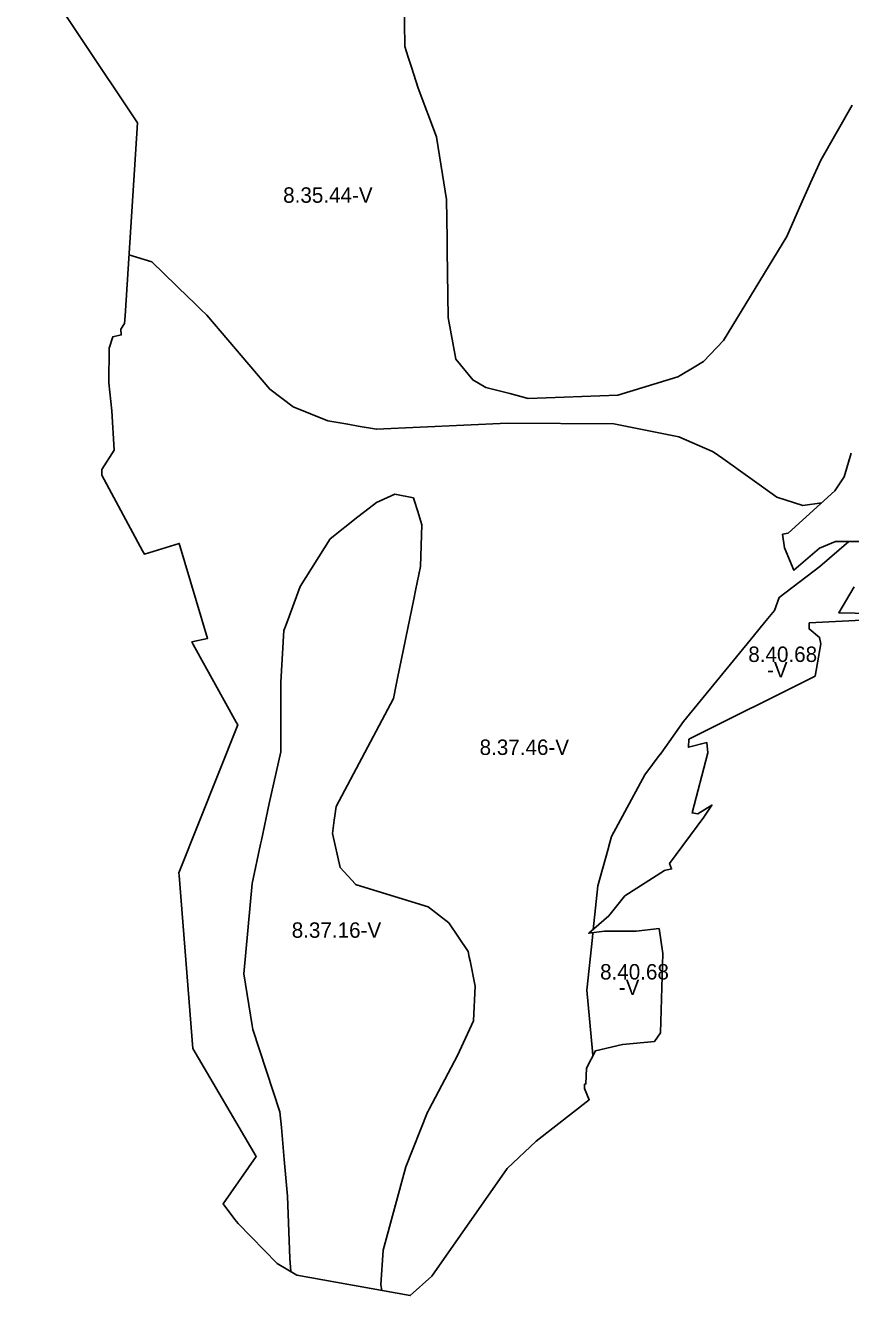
# Model space of a CAD drawing. Extents: x -547623 to -533936, y -1096714 to -1086523.
# Drawn here: x -545672 to -545138, y -1093937 to -1093114 of the extents above; entities that cross this region are included whole.
import ezdxf

# ---------------------------------------------------------------- set-up
doc = ezdxf.new("R2010")
doc.units = 0
doc.layers.add('Vrstva 27', color=7, linetype='Continuous')
doc.layers.add('Vrstva 28', color=7, linetype='Continuous')

msp = doc.modelspace()

# ---------------------------------------------------------------- linework, layer by layer
at = {"layer": 'Vrstva 28'}
for p, q in [((-545426.5, -1093127.5), (-545427, -1093096)), ((-545427, -1093096), (-545426.5, -1093127.5)), ((-545424.37, -1093134.25), (-545426.5, -1093127.5)), ((-545426.5, -1093127.5), (-545424.37, -1093134.25)), ((-545422.33, -1093140.76), (-545424.37, -1093134.25)), ((-545424.37, -1093134.25), (-545422.33, -1093140.76)), ((-545418, -1093154.5), (-545422.33, -1093140.76)), ((-545422.33, -1093140.76), (-545418, -1093154.5)), ((-545406, -1093186), (-545418, -1093154.5)), ((-545418, -1093154.5), (-545406, -1093186)), ((-545136.5, -1093165.5), (-545157, -1093201)), ((-545157, -1093201), (-545136.5, -1093165.5)), ((-545405.76, -1093187.52), (-545406, -1093186)), ((-545406, -1093186), (-545405.76, -1093187.52)), ((-545399.5, -1093226.5), (-545405.76, -1093187.52)), ((-545405.76, -1093187.52), (-545399.5, -1093226.5)), ((-545157, -1093201), (-545163.53, -1093215.69)), ((-545163.53, -1093215.69), (-545157, -1093201)), ((-545163.53, -1093215.69), (-545170.69, -1093231.81)), ((-545170.69, -1093231.81), (-545163.53, -1093215.69)), ((-545399.16, -1093252.14), (-545399.5, -1093226.5)), ((-545399.5, -1093226.5), (-545399.16, -1093252.14)), ((-545170.69, -1093231.81), (-545179, -1093250.5)), ((-545179, -1093250.5), (-545170.69, -1093231.81)), ((-545399.11, -1093256.04), (-545399.16, -1093252.14)), ((-545399.16, -1093252.14), (-545399.11, -1093256.04)), ((-545399.07, -1093259.54), (-545399.11, -1093256.04)), ((-545399.11, -1093256.04), (-545399.07, -1093259.54)), ((-545179, -1093250.5), (-545220, -1093318)), ((-545220, -1093318), (-545179, -1093250.5)), ((-545590.5, -1093267), (-545605.36, -1093262.54)), ((-545605.36, -1093262.54), (-545590.5, -1093267)), ((-545605.36, -1093262.54), (-545605.36, -1093262.54)), ((-545605.36, -1093262.54), (-545605.36, -1093262.54)), ((-545398.5, -1093303), (-545399.07, -1093259.54)), ((-545399.07, -1093259.54), (-545398.5, -1093303)), ((-545566.68, -1093290.14), (-545590.5, -1093267)), ((-545590.5, -1093267), (-545566.68, -1093290.14)), ((-545563.28, -1093293.45), (-545566.68, -1093290.14)), ((-545566.68, -1093290.14), (-545563.28, -1093293.45)), ((-545559.04, -1093297.57), (-545563.28, -1093293.45)), ((-545563.28, -1093293.45), (-545559.04, -1093297.57)), ((-545555, -1093301.5), (-545559.04, -1093297.57)), ((-545559.04, -1093297.57), (-545555, -1093301.5)), ((-545514, -1093349.5), (-545555, -1093301.5)), ((-545555, -1093301.5), (-545514, -1093349.5)), ((-545393.5, -1093330), (-545398.5, -1093303)), ((-545398.5, -1093303), (-545393.5, -1093330)), ((-545220, -1093318), (-545233, -1093331.5)), ((-545233, -1093331.5), (-545220, -1093318)), ((-545382.5, -1093343.5), (-545393.5, -1093330)), ((-545393.5, -1093330), (-545382.5, -1093343.5)), ((-545239.09, -1093335.19), (-545248.07, -1093340.63)), ((-545248.07, -1093340.63), (-545239.09, -1093335.19)), ((-545233, -1093331.5), (-545239.09, -1093335.19)), ((-545239.09, -1093335.19), (-545233, -1093331.5)), ((-545374, -1093348.5), (-545382.5, -1093343.5)), ((-545382.5, -1093343.5), (-545374, -1093348.5)), ((-545249.5, -1093341.5), (-545288.5, -1093353.5)), ((-545288.5, -1093353.5), (-545249.5, -1093341.5)), ((-545248.07, -1093340.63), (-545249.5, -1093341.5)), ((-545249.5, -1093341.5), (-545248.07, -1093340.63)), ((-545499, -1093361), (-545514, -1093349.5)), ((-545514, -1093349.5), (-545499, -1093361)), ((-545358.57, -1093352.43), (-545374, -1093348.5)), ((-545374, -1093348.5), (-545358.57, -1093352.43)), ((-545348.97, -1093354.87), (-545358.57, -1093352.43)), ((-545358.57, -1093352.43), (-545348.97, -1093354.87)), ((-545346.5, -1093355.5), (-545348.97, -1093354.87)), ((-545348.97, -1093354.87), (-545346.5, -1093355.5)), ((-545288.5, -1093353.5), (-545346.5, -1093355.5)), ((-545346.5, -1093355.5), (-545288.5, -1093353.5)), ((-545476.5, -1093370), (-545499, -1093361)), ((-545499, -1093361), (-545476.5, -1093370)), ((-545463.57, -1093372.26), (-545476.5, -1093370)), ((-545476.5, -1093370), (-545463.57, -1093372.26)), ((-545360, -1093371.5), (-545445, -1093375.5)), ((-545445, -1093375.5), (-545360, -1093371.5)), ((-545291, -1093372), (-545360, -1093371.5)), ((-545360, -1093371.5), (-545291, -1093372)), ((-545456.9, -1093373.42), (-545463.57, -1093372.26)), ((-545463.57, -1093372.26), (-545456.9, -1093373.42)), ((-545445, -1093375.5), (-545456.9, -1093373.42)), ((-545456.9, -1093373.42), (-545445, -1093375.5)), ((-545249, -1093380.5), (-545291, -1093372)), ((-545291, -1093372), (-545249, -1093380.5)), ((-545227.2, -1093389.98), (-545249, -1093380.5)), ((-545249, -1093380.5), (-545227.2, -1093389.98)), ((-545226, -1093390.5), (-545227.2, -1093389.98)), ((-545227.2, -1093389.98), (-545226, -1093390.5)), ((-545220.43, -1093394.49), (-545226, -1093390.5)), ((-545226, -1093390.5), (-545220.43, -1093394.49)), ((-545185.5, -1093419.5), (-545220.43, -1093394.49)), ((-545220.43, -1093394.49), (-545185.5, -1093419.5)), ((-545445, -1093423), (-545433, -1093417.5)), ((-545433, -1093417.5), (-545445, -1093423)), ((-545433, -1093417.5), (-545421, -1093420)), ((-545421, -1093420), (-545433, -1093417.5)), ((-545421, -1093420), (-545420.54, -1093421.46)), ((-545420.54, -1093421.46), (-545421, -1093420)), ((-545168.5, -1093425), (-545185.5, -1093419.5)), ((-545185.5, -1093419.5), (-545168.5, -1093425)), ((-545456.95, -1093432.36), (-545449.58, -1093426.59)), ((-545449.58, -1093426.59), (-545456.95, -1093432.36)), ((-545449.58, -1093426.59), (-545445, -1093423)), ((-545445, -1093423), (-545449.58, -1093426.59)), ((-545420.54, -1093421.46), (-545418.2, -1093428.91)), ((-545418.2, -1093428.91), (-545420.54, -1093421.46)), ((-545418.2, -1093428.91), (-545415.5, -1093437.5)), ((-545415.5, -1093437.5), (-545418.2, -1093428.91)), ((-545156.28, -1093423.14), (-545168.5, -1093425)), ((-545168.5, -1093425), (-545156.28, -1093423.14)), ((-545156.28, -1093423.14), (-545156.28, -1093423.14)), ((-545156.28, -1093423.14), (-545156.28, -1093423.14)), ((-545475, -1093446.5), (-545456.95, -1093432.36)), ((-545456.95, -1093432.36), (-545475, -1093446.5)), ((-545415.5, -1093437.5), (-545416.5, -1093464.5)), ((-545416.5, -1093464.5), (-545415.5, -1093437.5)), ((-545494.5, -1093477.5), (-545475, -1093446.5)), ((-545475, -1093446.5), (-545494.5, -1093477.5)), ((-545138.7, -1093448.27), (-545157.5, -1093464.5)), ((-545157.5, -1093464.5), (-545138.7, -1093448.27)), ((-545416.5, -1093464.5), (-545419.69, -1093480.07)), ((-545419.69, -1093480.07), (-545416.5, -1093464.5)), ((-545157.5, -1093464.5), (-545184, -1093484.5)), ((-545184, -1093484.5), (-545157.5, -1093464.5)), ((-545503.14, -1093500.95), (-545494.5, -1093477.5)), ((-545494.5, -1093477.5), (-545503.14, -1093500.95)), ((-545420.81, -1093485.54), (-545431.29, -1093536.75)), ((-545431.29, -1093536.75), (-545420.81, -1093485.54)), ((-545419.69, -1093480.07), (-545420.81, -1093485.54)), ((-545420.81, -1093485.54), (-545419.69, -1093480.07)), ((-545184, -1093484.5), (-545187, -1093493)), ((-545187, -1093493), (-545184, -1093484.5)), ((-545187, -1093493), (-545193.38, -1093500.79)), ((-545193.38, -1093500.79), (-545187, -1093493)), ((-545504.56, -1093504.8), (-545503.14, -1093500.95)), ((-545503.14, -1093500.95), (-545504.56, -1093504.8)), ((-545193.38, -1093500.79), (-545200.78, -1093509.82)), ((-545200.78, -1093509.82), (-545193.38, -1093500.79)), ((-545507, -1093539.5), (-545505, -1093506)), ((-545505, -1093506), (-545507, -1093539.5)), ((-545505, -1093506), (-545504.56, -1093504.8)), ((-545504.56, -1093504.8), (-545505, -1093506)), ((-545200.78, -1093509.82), (-545246, -1093565)), ((-545246, -1093565), (-545200.78, -1093509.82)), ((-545507, -1093558.91), (-545507, -1093539.5)), ((-545507, -1093539.5), (-545507, -1093558.91)), ((-545432.18, -1093541.09), (-545434, -1093550)), ((-545434, -1093550), (-545432.18, -1093541.09)), ((-545431.29, -1093536.75), (-545432.18, -1093541.09)), ((-545432.18, -1093541.09), (-545431.29, -1093536.75)), ((-545434, -1093550), (-545471, -1093620)), ((-545471, -1093620), (-545434, -1093550)), ((-545507, -1093561.31), (-545507, -1093558.91)), ((-545507, -1093558.91), (-545507, -1093561.31)), ((-545507, -1093584.5), (-545507, -1093561.31)), ((-545507, -1093561.31), (-545507, -1093584.5)), ((-545246, -1093565), (-545260.5, -1093585.5)), ((-545260.5, -1093585.5), (-545246, -1093565)), ((-545514.5, -1093618), (-545507, -1093584.5)), ((-545507, -1093584.5), (-545514.5, -1093618)), ((-545260.5, -1093585.5), (-545260.93, -1093586.12)), ((-545260.93, -1093586.12), (-545260.5, -1093585.5)), ((-545260.97, -1093586.13), (-545270.95, -1093599.45)), ((-545270.95, -1093599.45), (-545260.97, -1093586.13)), ((-545260.93, -1093586.12), (-545260.97, -1093586.13)), ((-545260.97, -1093586.13), (-545260.93, -1093586.12)), ((-545271, -1093599.5), (-545292.5, -1093639.5)), ((-545292.5, -1093639.5), (-545271, -1093599.5)), ((-545270.95, -1093599.45), (-545271, -1093599.5)), ((-545271, -1093599.5), (-545270.95, -1093599.45)), ((-545519.53, -1093641.76), (-545514.5, -1093618)), ((-545514.5, -1093618), (-545519.53, -1093641.76)), ((-545471.88, -1093626.14), (-545472.28, -1093628.97)), ((-545472.28, -1093628.97), (-545471.88, -1093626.14)), ((-545471, -1093620), (-545471.88, -1093626.14)), ((-545471.88, -1093626.14), (-545471, -1093620)), ((-545472.28, -1093628.97), (-545473.5, -1093637.5)), ((-545473.5, -1093637.5), (-545472.28, -1093628.97)), ((-545520.09, -1093644.43), (-545519.53, -1093641.76)), ((-545519.53, -1093641.76), (-545520.09, -1093644.43)), ((-545473.5, -1093637.5), (-545468.5, -1093659.5)), ((-545468.5, -1093659.5), (-545473.5, -1093637.5)), ((-545292.5, -1093639.5), (-545293.59, -1093643.39)), ((-545293.59, -1093643.39), (-545292.5, -1093639.5)), ((-545525.5, -1093670), (-545520.09, -1093644.43)), ((-545520.09, -1093644.43), (-545525.5, -1093670)), ((-545295, -1093648.41), (-545301.5, -1093671.5)), ((-545301.5, -1093671.5), (-545295, -1093648.41)), ((-545293.59, -1093643.39), (-545295, -1093648.41)), ((-545295, -1093648.41), (-545293.59, -1093643.39)), ((-545468.5, -1093659.5), (-545458.55, -1093670.45)), ((-545458.55, -1093670.45), (-545468.5, -1093659.5)), ((-545531, -1093728.5), (-545525.5, -1093670)), ((-545525.5, -1093670), (-545531, -1093728.5)), ((-545458.55, -1093670.45), (-545458.5, -1093670.5)), ((-545458.5, -1093670.5), (-545458.55, -1093670.45)), ((-545458.5, -1093670.5), (-545455.1, -1093671.55)), ((-545455.1, -1093671.55), (-545458.5, -1093670.5)), ((-545455.1, -1093671.55), (-545411.5, -1093685)), ((-545411.5, -1093685), (-545455.1, -1093671.55)), ((-545301.5, -1093671.5), (-545304.03, -1093695.87)), ((-545304.03, -1093695.87), (-545301.5, -1093671.5)), ((-545411.5, -1093685), (-545398, -1093695.5)), ((-545398, -1093695.5), (-545411.5, -1093685)), ((-545398, -1093695.5), (-545385.5, -1093714)), ((-545385.5, -1093714), (-545398, -1093695.5)), ((-545304.03, -1093695.87), (-545304.43, -1093699.71)), ((-545304.43, -1093699.71), (-545304.03, -1093695.87)), ((-545304.43, -1093699.71), (-545304.43, -1093699.71)), ((-545304.43, -1093699.71), (-545304.43, -1093699.71)), ((-545304.96, -1093704.83), (-545308.5, -1093739)), ((-545308.5, -1093739), (-545304.96, -1093704.83)), ((-545304.65, -1093701.84), (-545304.96, -1093704.83)), ((-545304.96, -1093704.83), (-545304.65, -1093701.84)), ((-545385.5, -1093714), (-545384.79, -1093717.56)), ((-545384.79, -1093717.56), (-545385.5, -1093714)), ((-545384.79, -1093717.56), (-545384.28, -1093720.09)), ((-545384.28, -1093720.09), (-545384.79, -1093717.56)), ((-545384.28, -1093720.09), (-545381, -1093736.5)), ((-545381, -1093736.5), (-545384.28, -1093720.09)), ((-545525.42, -1093761.97), (-545531, -1093728.5)), ((-545531, -1093728.5), (-545525.42, -1093761.97)), ((-545381, -1093736.5), (-545382, -1093759)), ((-545382, -1093759), (-545381, -1093736.5)), ((-545308.5, -1093739), (-545305, -1093778.5)), ((-545305, -1093778.5), (-545308.5, -1093739)), ((-545525, -1093764.5), (-545525.42, -1093761.97)), ((-545525.42, -1093761.97), (-545525, -1093764.5)), ((-545507.5, -1093818), (-545525, -1093764.5)), ((-545525, -1093764.5), (-545507.5, -1093818)), ((-545382, -1093759), (-545392.5, -1093781.5)), ((-545392.5, -1093781.5), (-545382, -1093759)), ((-545392.5, -1093781.5), (-545410.77, -1093816.11)), ((-545410.77, -1093816.11), (-545392.5, -1093781.5)), ((-545305, -1093778.5), (-545304.78, -1093781.97)), ((-545304.78, -1093781.97), (-545305, -1093778.5)), ((-545410.77, -1093816.11), (-545411.5, -1093817.5)), ((-545411.5, -1093817.5), (-545410.77, -1093816.11)), ((-545506.57, -1093828.11), (-545507.5, -1093818)), ((-545507.5, -1093818), (-545506.57, -1093828.11)), ((-545411.79, -1093818.23), (-545426, -1093853.5)), ((-545426, -1093853.5), (-545411.79, -1093818.23)), ((-545411.5, -1093817.5), (-545411.79, -1093818.23)), ((-545411.79, -1093818.23), (-545411.5, -1093817.5)), ((-545504.68, -1093848.73), (-545506.57, -1093828.11)), ((-545506.57, -1093828.11), (-545504.68, -1093848.73)), ((-545502.5, -1093872.5), (-545504.68, -1093848.73)), ((-545504.68, -1093848.73), (-545502.5, -1093872.5)), ((-545426, -1093853.5), (-545440.5, -1093907.5)), ((-545440.5, -1093907.5), (-545426, -1093853.5)), ((-545501, -1093913), (-545502.5, -1093872.5)), ((-545502.5, -1093872.5), (-545501, -1093913)), ((-545500.53, -1093921.4), (-545501, -1093913)), ((-545501, -1093913), (-545500.53, -1093921.4)), ((-545440.5, -1093907.5), (-545442, -1093930)), ((-545442, -1093930), (-545440.5, -1093907.5)), ((-545500.53, -1093921.4), (-545500.53, -1093921.4)), ((-545500.53, -1093921.4), (-545500.53, -1093921.4)), ((-545442, -1093930), (-545441.5, -1093933.5)), ((-545441.5, -1093933.5), (-545442, -1093930)), ((-545441.46, -1093933.69), (-545441.5, -1093933.5))]:
    msp.add_line(p, q, dxfattribs=at)
for points in [[(-545126.09, -1093499.13), (-545164.4, -1093501), (-545164.5, -1093504.95), (-545157.74, -1093510.41), (-545156.8, -1093514.62), (-545160.61, -1093535.52), (-545242.4, -1093576.43), (-545242.76, -1093581.56), (-545230.69, -1093578.53), (-545230.19, -1093585.13), (-545240.37, -1093624.12), (-545236.55, -1093624.74), (-545227.49, -1093619.05), (-545232.79, -1093626.89), (-545254.89, -1093656.92), (-545253.69, -1093660.51), (-545258.16, -1093661.55), (-545283.9, -1093677.96), (-545294.29, -1093690.93), (-545307.31, -1093702.21), (-545297.02, -1093700.77), (-545276.64, -1093700.87), (-545261.74, -1093699.14), (-545259.28, -1093715.32), (-545260.83, -1093766.7), (-545264.81, -1093772.22), (-545285.4, -1093774.23), (-545302.9, -1093778.34), (-545308.74, -1093789.65), (-545309.21, -1093799.86), (-545310.04, -1093799.95), (-545310.04, -1093802.69), (-545307.02, -1093810.11), (-545341.46, -1093836.83), (-545360.16, -1093854.55), (-545409.05, -1093924.38), (-545423.03, -1093937.01), (-545496.58, -1093923.75), (-545509.31, -1093916.19), (-545534.66, -1093890.25), (-545536.67, -1093887.6), (-545544.36, -1093877.46), (-545523, -1093846.89), (-545564.04, -1093776.79), (-545572.87, -1093664.63), (-545572.99, -1093663.08), (-545572.53, -1093661.93), (-545534.86, -1093567.12), (-545535.89, -1093565.25), (-545563.65, -1093515.02), (-545564.61, -1093513.24), (-545554.37, -1093511.1), (-545572.78, -1093449.47), (-545595.37, -1093456.39), (-545596.5, -1093454.3), (-545622.96, -1093405.34), (-545622.85, -1093401.58), (-545615.04, -1093389), (-545616.56, -1093363.57), (-545618.46, -1093345.39), (-545618.1, -1093322.84), (-545615.88, -1093315.57), (-545610.32, -1093314.39), (-545610.68, -1093310.56), (-545608.22, -1093307.01), (-545607.9, -1093302.04), (-545599.87, -1093177), (-545672.5, -1093068.01)], [(-545136.5, -1093165.5), (-545157, -1093201), (-545163.53, -1093215.69), (-545170.69, -1093231.81), (-545179, -1093250.5), (-545220, -1093318), (-545233, -1093331.5), (-545239.09, -1093335.19), (-545248.07, -1093340.63), (-545249.5, -1093341.5), (-545288.5, -1093353.5), (-545346.5, -1093355.5), (-545348.97, -1093354.87), (-545358.57, -1093352.43), (-545374, -1093348.5), (-545382.5, -1093343.5), (-545393.5, -1093330), (-545398.5, -1093303), (-545399.07, -1093259.54), (-545399.11, -1093256.04), (-545399.16, -1093252.14), (-545399.5, -1093226.5), (-545405.76, -1093187.52), (-545406, -1093186), (-545418, -1093154.5), (-545422.33, -1093140.76), (-545424.37, -1093134.25), (-545426.5, -1093127.5), (-545427, -1093096)], [(-545291, -1093372), (-545360, -1093371.5), (-545445, -1093375.5), (-545456.9, -1093373.42), (-545463.57, -1093372.26), (-545476.5, -1093370), (-545499, -1093361), (-545514, -1093349.5), (-545555, -1093301.5), (-545559.04, -1093297.57), (-545563.28, -1093293.45), (-545566.68, -1093290.14), (-545590.5, -1093267), (-545605.36, -1093262.54), (-545605.36, -1093262.54)], [(-545605.36, -1093262.54), (-545605.36, -1093262.54), (-545590.5, -1093267), (-545566.68, -1093290.14), (-545563.28, -1093293.45), (-545559.04, -1093297.57), (-545555, -1093301.5), (-545514, -1093349.5), (-545499, -1093361), (-545476.5, -1093370), (-545463.57, -1093372.26), (-545456.9, -1093373.42), (-545445, -1093375.5), (-545360, -1093371.5), (-545291, -1093372), (-545249, -1093380.5), (-545227.2, -1093389.98), (-545226, -1093390.5), (-545220.43, -1093394.49), (-545185.5, -1093419.5), (-545168.5, -1093425), (-545156.28, -1093423.14), (-545156.28, -1093423.14)], [(-545156.28, -1093423.14), (-545156.28, -1093423.14), (-545168.5, -1093425), (-545185.5, -1093419.5), (-545220.43, -1093394.49), (-545226, -1093390.5), (-545227.2, -1093389.98), (-545249, -1093380.5), (-545291, -1093372)], [(-545137.32, -1093390.95), (-545141.73, -1093406.38), (-545147.83, -1093415.52), (-545178.09, -1093442.8), (-545181.74, -1093443.51), (-545180.54, -1093452.43), (-545174.29, -1093466.92), (-545157.82, -1093452.49), (-545147.44, -1093448.25), (-545131.6, -1093448.28)], [(-545304.43, -1093699.71), (-545304.43, -1093699.71), (-545304.03, -1093695.87), (-545301.5, -1093671.5), (-545295, -1093648.41), (-545293.59, -1093643.39), (-545292.5, -1093639.5), (-545271, -1093599.5), (-545270.95, -1093599.45), (-545260.97, -1093586.13), (-545260.93, -1093586.12), (-545260.5, -1093585.5), (-545246, -1093565), (-545200.78, -1093509.82), (-545193.38, -1093500.79), (-545187, -1093493), (-545184, -1093484.5), (-545157.5, -1093464.5), (-545138.7, -1093448.27)], [(-545135.36, -1093477.57), (-545145.3, -1093494.44), (-545124.01, -1093494.97)], [(-545304.78, -1093781.97), (-545305, -1093778.5), (-545308.5, -1093739), (-545304.96, -1093704.83), (-545304.65, -1093701.84)]]:
    msp.add_lwpolyline(points, dxfattribs=at)

# ---------------------------------------------------------------- texts
at = {"layer": 'Vrstva 27'}
for s, p in [('8.35.44-V', (-545505.41, -1093228.71)), ('8.40.68', (-545203.92, -1093526.33)), ('-V', (-545191.79, -1093536.33)), ('8.37.46-V', (-545378.08, -1093586.6)), ('8.37.16-V', (-545499.86, -1093705.11)), ('8.40.68', (-545299.99, -1093732.14)), ('-V', (-545287.86, -1093742.14))]:
    msp.add_text(s, height=10, dxfattribs=at).set_placement(p)

doc.saveas('drawing.dxf')
